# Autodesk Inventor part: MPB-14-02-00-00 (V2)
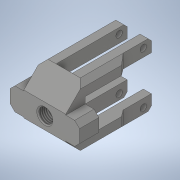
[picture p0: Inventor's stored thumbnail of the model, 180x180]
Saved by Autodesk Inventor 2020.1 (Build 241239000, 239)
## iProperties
Created: 2020-04
Part Number: MPB-14-02-00-00 (V2)
Material: Al 7075
Document SubType Name: Modeling
Designer: Safarabadi
Density: 2.7 g/cm^3
Appearance: Aluminum - Flat
Author: Safarabadi
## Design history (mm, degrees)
derived "MPB-14-02-00-00.ipt"
feature "Solid1::MPB-14-02-00-00.ipt" dims "d0" = 10
tag "TaggingFeature1"
body "Solid1"
